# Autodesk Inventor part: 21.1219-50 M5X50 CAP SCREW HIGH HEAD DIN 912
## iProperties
IsCustomPart: 1
Created: 2006-02
Part Number: 21.1219-50 M5X50 CAP SCREW HIGH HEAD DIN 912
Material: Steel, Mild
Description: Cylinder Head Cap Screw
Document SubType Name: Modeling
Standard: DIN 912
Designer: Andy Moles
Standards Organization: DIN
Language: en-US
Size Designation: M5 x 50
Categories: <MemberInstance><Categories><Category DisplayName="Fasteners" InternalName="e4da775c-781d-43d5-af7c-5136215cf5a6" Mnemonic="FSTN"><Category DisplayName="Bolts"
Density: 1 g/cm^3
Author: Andy Moles
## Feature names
1. Body [Revolution]
2. Slot [Extrusion]
3. Fillet1
4. Chamfer1
